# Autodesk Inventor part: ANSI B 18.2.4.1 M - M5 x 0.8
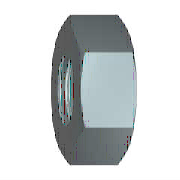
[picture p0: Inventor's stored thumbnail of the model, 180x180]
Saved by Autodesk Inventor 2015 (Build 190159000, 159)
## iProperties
Created: 2014-02
Part Number: ANSI B 18.2.4.1 M - M5 x 0.8
Material: Steel, Mild
Description: Hex Nut
Document SubType Name: Modeling
Standard: ANSI B 18.2.4.1 M
Designer: rsheridan
Standards Organization: ANSI
Language: en-US
Size Designation: M5 x 0.8
Categories: <MemberInstance><Categories><Category DisplayName="Fasteners" InternalName="e4da775c-781d-43d5-af7c-5136215cf5a6" Mnemonic="FSTN"><Category DisplayName="Nuts" I
Density: 1 g/cm^3
Appearance: Semi-Polished
IsCustomPart: 1
Author: rsheridan
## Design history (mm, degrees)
sketch "Sketch1"
  geometry: L1 (-4.619, 0)-(-2.309, 4); L2 (-2.309, 4)-(2.309, 4); L3 (2.309, 4)-(4.619, 0); L4 (4.619, 0)-(2.309, -4); L5 (2.309, -4)-(-2.309, -4); L6 (-2.309, -4)-(-4.619, 0); 2 further points
  constraints: 12 end point, 1 coincident, 1 horizontal, 11 other
  dimensions: "d0" = 9.2376 distance of L3.end L1.start (= 1.1547 x SW)
extrude "Body" new body sketch "Sketch1" distance "d1" = 4.7 (= KOH); taper "d2" = 0 deg
sketch "Sketch2"
  geometry: L1 (0, 2.309)-(0, 4.619) reference; L2 (0, 4.619)-(4.7, 4.619) reference; L3 (4.7, 2.309)-(4.7, 4.619) reference; L4 (-0.94, 0)-(5.64, 0) reference; L5 (0.289, 4.619)-(0, 4); L6 (4.411, 4.619)-(4.7, 4)
  constraints: 4 end point, 4 point on line
  dimensions: "d3" = 25 deg angle of L1 L5 (= ANG1); "d4" = 25 deg angle of L3 L6 (= ANG2); "d5" = 8 diameter of L5.end L4 (= SW0); "d6" = 8 diameter of L6.end L4 (= SW01)
revolve "Chamfer1" sketch "Sketch2" stored, may be unused: angle "d7" = 90 deg
sketch "Sketch3"
  geometry: A1 r 4 centre (0, 0) between (-2, -3.464) and (2, -3.464) reference; 1 further point
  constraints: 1 coincident
hole "Thread" sketch "Sketch3" at (0, 0) diameter "d25" = 4.134; stored, may be unused: countersink angle "d29" = 82 deg, drill point angle "d31" = 118 deg; dims "d26" = 6, "d27" = 4, "d28" = 2, "d30" = 8
workaxis "Work Axis1"
workplane "Work Plane1"
body "Solid1"
chamfer "Chamfer2" distance "d8" = 0.43301 (= -0.5 x GD1 + 0.5 x NND); stored, may be unused: angle "d9" = 30 deg, second distance "d40" = 0.43301 (= -0.5 x GD1 + 0.5 x NND)
chamfer "Chamfer3" distance "d10" = 0.43301 (= -0.5 x GD1 + 0.5 x NND); stored, may be unused: angle "d11" = 30 deg, second distance "d41" = 0.43301 (= -0.5 x GD1 + 0.5 x NND)
other parameters: "ANG1" = 25 deg [user parameter; used in 1 equation term], "ANG2" = 25 deg [user parameter; used in 1 equation term], "NND" = 5 [user parameter; used in 4 equation terms], "KOH" = 4.7 [user parameter; used in 1 equation term], "SW" = 8 [user parameter; used in 4 equation terms], "SW0" = 8 (= SW) [user parameter; used in 1 equation term], "SW01" = 8 (= SW) [user parameter; used in 1 equation term], "GD1" = 4.13397 (computed from THREADDIA, PTC, TOA) [user parameter; used in 4 equation terms], "d13" = 0, "d14" = 0, "d39" = 0, "d42" = 0, "GUL" = 0.43301 (= 0.541266 x PTC) [user parameter], "TPU" = 12.5 (computed from PTC) [user parameter], "THREADDIA" = 5 [user parameter; used in 1 equation term], "TOA" = 30 deg [user parameter; used in 1 equation term], "PTC" = 0.8 [user parameter; used in 4 equation terms], "E0" = 9.24 (= 1.155 x SW) [user parameter], "GAL" = 0.43301 (= 0.541266 x PTC) [user parameter], "SD2" = 0 [user parameter], "WFT" = 0 [user parameter]
